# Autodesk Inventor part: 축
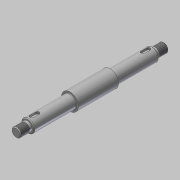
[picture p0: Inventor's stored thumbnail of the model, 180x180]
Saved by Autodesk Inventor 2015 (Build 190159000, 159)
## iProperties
Created: 2018-11
Part Number: 축
Material: 강철, 연강
Document SubType Name: Modeling
Designer: mduedu
Density: 1 g/cm^3
Appearance: 강철
Author: mduedu
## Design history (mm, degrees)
sketch "스케치1"
  geometry: L1 (-26, 0)-(26, 0); L2 (26, 0)-(26, 11); L3 (26, 11)-(-26, 11); L4 (-26, 11)-(-26, 0); L5 (-26, 0)-(-81, 0); L6 (-81, 0)-(-81, 8.5); L7 (-81, 8.5)-(-26, 8.5); L8 (-26, 8.5)-(-26, 0); L9 (-81, 0)-(-96, 0); L10 (-96, 0)-(-96, 6); L11 (-96, 6)-(-81, 6); L12 (-81, 6)-(-81, 0); L13 (0, 0)-(0, 11); L14 (26, 0)-(81, 0); L15 (81, 0)-(81, 8.5); L16 (81, 8.5)-(26, 8.5); L17 (26, 8.5)-(26, 0); L18 (81, 0)-(96, 0); L19 (96, 0)-(96, 6); L20 (96, 6)-(81, 6); L21 (81, 6)-(81, 0); 1 further point
  constraints: 42 end point, 6 parallel, 6 symmetric about line, 3 horizontal, 3 perpendicular, 2 midpoint, 1 coincident
  dimensions: "d0" = 22 diameter of L3 L1; "d2" = 17 diameter of L7 L5; "d3" = 12 diameter of L11 L9; "d4" = 52 distance of L2.end L3.end; "d5" = 55 distance of L6.end L7.end; "d6" = 192 distance between parallel lines of L19 L10
revolve "회전1" sketch "스케치1" stored, may be unused: angle "d7" = 90 deg
fillet "모깎기1" dims "d8" = 0.6
node "작업 평면1"
sketch "스케치2" dims "d11" = 12
  geometry: L1 (15, 2.5)-(22, 2.5); L2 (22, 2.5)-(22, -2.5); L3 (22, -2.5)-(15, -2.5); L4 (15, -2.5)-(15, 2.5); L5 (27.5, 8.5)-(27.5, -8.5) reference; 3 further points
  constraints: 8 end point, 2 midpoint, 2 parallel, 2 vertical alignment, 1 horizontal, 1 horizontal alignment, 1 perpendicular, 4 other
  dimensions: "d9" = 3 dimension on L5; "d10" = 5 distance between parallel lines of L3 L1
extrude "돌출1" cut sketch "스케치2" distance "d12" = 3; taper "d13" = 0 deg
chamfer "모따기1" distance "d14" = 1; stored, may be unused: second distance "d15" = 2, angle "d16" = 45 deg
feature "스레드1" dims "d17" = 12, "d18" = 0
feature "스레드2" dims "d19" = 12, "d20" = 0
chamfer "모따기2" distance "d21" = 1; stored, may be unused: second distance "d22" = 2, angle "d23" = 45 deg
node "솔리드1"
mirror "대칭1"
